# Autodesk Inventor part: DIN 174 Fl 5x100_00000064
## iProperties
Created: 2006-03
Part Number: DIN 174 Fl 5x100_00000064
Material: Default
Document SubType Name: Modeling
Designer: Carlo
Stock Number: DIN 174 Fl 5x100
Mass: 1018.85 g
Surface Area: 4289.58 cm^2
Volume: 1018.85 cm^3
Density: 1 g/cm^3
G_L: 2037.896 mm
G_W: 5.000 mm
G_H: 100.000 mm
AFG_Item: 100 x 5
CSToolsMass: 1.0
CSToolsVolume: 1018849.0
CSToolsArea: 4290.0
Author: Carlo
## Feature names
1. AFG_Detailed_DIN 174 Fl 5x100_00000064 [Extrusion]
2. AFG_Simplified_DIN 174 Fl 5x100_00000064 [Extrusion]
3. AFG_StartExtrusion_1 [Extrusion]
4. AFG_StartExtrusion_2 [Extrusion]
5. AFG_EndExtrusion_1 [Extrusion]
6. AFG_EndExtrusion_2 [Extrusion]
